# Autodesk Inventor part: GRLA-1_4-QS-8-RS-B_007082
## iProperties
Created: 2005-05
Part Number: GRLA-1_4-QS-8-RS-B_007082
Document SubType Name: Modeling
Designer: tfa
Manufacturer: Standard
Standards Organization: Custom
Author: tfa
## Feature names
1. Basis1
